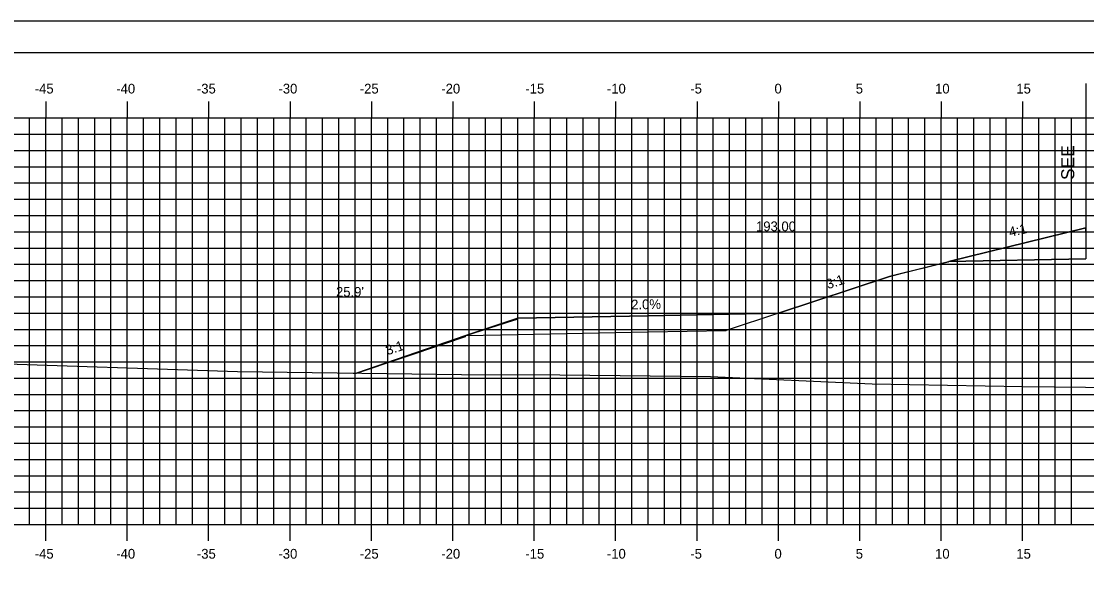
# Model space of a CAD drawing. Extents: x 1723764 to 1723936, y 458501 to 458611.
# Drawn here: x 1723801 to 1723866.5, y 458577.5 to 458611.2 of the extents above; entities that cross this region are included whole.
import ezdxf

# ---------------------------------------------------------------- set-up
doc = ezdxf.new("R2010")
doc.units = 0
for name, color, linetype in [('ANNOTATION', 7, 'Continuous'), ('BORDER', 7, 'Continuous'), ('D_Roadway_Centerline', 7, 'Continuous'), ('D_Roadway_Centerline_Text', 7, 'Continuous'), ('D_Roadway_Drive_Gravel', 7, 'Continuous'), ('D_Roadway_Edge_Shoulder', 7, 'Continuous'), ('D_Roadway_SlopeLines', 7, 'Continuous'), ('D_Roadway_SubGrade', 7, 'Continuous'), ('D_Text_Standard', 7, 'Continuous'), ('H_V ANNOTATION', 7, 'Continuous'), ('MAJOR', 7, 'Continuous'), ('MINOR', 7, 'Continuous'), ('PLOT BOUNDARY', 7, 'Continuous'), ('S_Roadway_Centerline', 7, 'Continuous')]:
    doc.layers.add(name, color=color, linetype=linetype)

msp = doc.modelspace()

# ---------------------------------------------------------------- linework, layer by layer
msp.add_lwpolyline([(1723821.421, 458589.561), (1723821.421, 458589.561), (1723821.615, 458589.558), (1723827.107, 458591.403), (1723828.318, 458591.81), (1723828.351, 458591.871), (1723828.35, 458591.871), (1723831.296, 458592.815), (1723831.513, 458592.887), (1723831.542, 458592.934), (1723839.542, 458593.094), (1723847.542, 458593.254), (1723847.542, 458593.254), (1723847.542, 458593.254)])
at = {"layer": 'BORDER'}
msp.add_lwpolyline([(1723772.542, 458504.254), (1723932.542, 458504.254), (1723932.542, 458609.254), (1723772.542, 458609.254)], close=True, dxfattribs=at)
at = {"layer": 'D_Roadway_Centerline'}
msp.add_lwpolyline([(1723847.542, 458593.254), (1723854.363, 458595.513), (1723855.146, 458595.707), (1723857.368, 458596.259), (1723857.45, 458596.279), (1723857.892, 458596.389), (1723857.983, 458596.412), (1723858.017, 458596.42), (1723862.494, 458597.531), (1723866.419, 458598.505)], dxfattribs=at)
at = {"layer": 'D_Roadway_Drive_Gravel'}
msp.add_lwpolyline([(1723847.542, 458593.254), (1723839.542, 458593.094), (1723831.542, 458592.934), (1723828.35, 458591.871), (1723831.542, 458591.934), (1723839.542, 458592.094), (1723844.328, 458592.19)], dxfattribs=at)
at = {"layer": 'D_Roadway_Edge_Shoulder'}
msp.add_line((1723866.419, 458598.505), (1723866.419, 458598.255), dxfattribs=at)
msp.add_line((1723866.419, 458598.505), (1723866.419, 458598.255), dxfattribs=at)
at = {"layer": 'D_Roadway_SlopeLines'}
msp.add_line((1723847.542, 458593.254), (1723844.328, 458592.19), dxfattribs=at)
for points in [[(1723866.419, 458598.505), (1723854.363, 458595.513), (1723847.542, 458593.254)], [(1723866.419, 458598.505), (1723854.363, 458595.513), (1723847.542, 458593.254)], [(1723866.419, 458598.505), (1723854.363, 458595.513), (1723847.542, 458593.254)], [(1723866.419, 458598.505), (1723854.363, 458595.513), (1723847.542, 458593.254)], [(1723866.419, 458598.505), (1723854.363, 458595.513), (1723847.542, 458593.254)], [(1723866.419, 458598.505), (1723854.363, 458595.513), (1723847.542, 458593.254)], [(1723866.419, 458598.505), (1723854.363, 458595.513)], [(1723866.419, 458598.505), (1723854.363, 458595.513)], [(1723866.419, 458598.505), (1723858.017, 458596.42)], [(1723847.542, 458593.254), (1723847.542, 458593.254)], [(1723831.542, 458592.934), (1723828.35, 458591.871), (1723821.615, 458589.558)]]:
    msp.add_lwpolyline(points, dxfattribs=at)
at = {"layer": 'D_Roadway_SubGrade'}
msp.add_line((1723866.419, 458607.364), (1723866.419, 458596.582), dxfattribs=at)
for points in [[(1723866.419, 458596.582), (1723858.017, 458596.42), (1723866.419, 458598.505), (1723866.419, 458598.255)], [(1723866.419, 458598.255), (1723866.419, 458598.505), (1723858.017, 458596.42), (1723866.419, 458596.582)], [(1723866.419, 458596.582), (1723858.017, 458596.42), (1723866.419, 458598.505), (1723866.419, 458598.255)], [(1723866.419, 458596.582), (1723858.017, 458596.42), (1723866.419, 458598.505), (1723866.419, 458598.255)]]:
    msp.add_lwpolyline(points, dxfattribs=at)
at = {"layer": 'MAJOR'}
for p, q in [((1723802.542, 458606.256), (1723802.542, 458605.254)), ((1723807.542, 458606.256), (1723807.542, 458605.254)), ((1723812.542, 458606.256), (1723812.542, 458605.254)), ((1723817.542, 458606.256), (1723817.542, 458605.254)), ((1723822.542, 458606.256), (1723822.542, 458605.254)), ((1723827.542, 458606.256), (1723827.542, 458605.254)), ((1723832.542, 458606.256), (1723832.542, 458605.254)), ((1723837.542, 458606.256), (1723837.542, 458605.254)), ((1723842.542, 458606.256), (1723842.542, 458605.254)), ((1723847.542, 458606.256), (1723847.542, 458605.254)), ((1723852.542, 458606.256), (1723852.542, 458605.254)), ((1723857.542, 458606.256), (1723857.542, 458605.254)), ((1723862.542, 458606.256), (1723862.542, 458605.254)), ((1723777.542, 458605.254), (1723917.542, 458605.254)), ((1723777.542, 458605.254), (1723917.542, 458605.254)), ((1723802.542, 458580.254), (1723802.542, 458605.254)), ((1723807.542, 458580.254), (1723807.542, 458605.254)), ((1723812.542, 458580.254), (1723812.542, 458605.254)), ((1723817.542, 458580.254), (1723817.542, 458605.254)), ((1723822.542, 458580.254), (1723822.542, 458605.254)), ((1723827.542, 458580.254), (1723827.542, 458605.254)), ((1723832.542, 458580.254), (1723832.542, 458605.254)), ((1723837.542, 458580.254), (1723837.542, 458605.254)), ((1723842.542, 458580.254), (1723842.542, 458605.254)), ((1723847.542, 458580.254), (1723847.542, 458605.254)), ((1723852.542, 458580.254), (1723852.542, 458605.254)), ((1723857.542, 458580.254), (1723857.542, 458605.254)), ((1723862.542, 458580.254), (1723862.542, 458605.254)), ((1723777.542, 458600.254), (1723917.542, 458600.254)), ((1723777.542, 458595.254), (1723917.542, 458595.254)), ((1723777.542, 458590.254), (1723917.542, 458590.254)), ((1723777.542, 458585.254), (1723917.542, 458585.254)), ((1723777.542, 458580.254), (1723917.542, 458580.254)), ((1723777.542, 458580.254), (1723917.542, 458580.254)), ((1723802.542, 458579.252), (1723802.542, 458580.254)), ((1723807.542, 458579.252), (1723807.542, 458580.254)), ((1723812.542, 458579.252), (1723812.542, 458580.254)), ((1723817.542, 458579.252), (1723817.542, 458580.254)), ((1723822.542, 458579.252), (1723822.542, 458580.254)), ((1723827.542, 458579.252), (1723827.542, 458580.254)), ((1723832.542, 458579.252), (1723832.542, 458580.254)), ((1723837.542, 458579.252), (1723837.542, 458580.254)), ((1723842.542, 458579.252), (1723842.542, 458580.254)), ((1723847.542, 458579.252), (1723847.542, 458580.254)), ((1723852.542, 458579.252), (1723852.542, 458580.254)), ((1723857.542, 458579.252), (1723857.542, 458580.254)), ((1723862.542, 458579.252), (1723862.542, 458580.254))]:
    msp.add_line(p, q, dxfattribs=at)
at = {"layer": 'MINOR'}
for p, q in [((1723801.542, 458580.254), (1723801.542, 458605.254)), ((1723803.542, 458580.254), (1723803.542, 458605.254)), ((1723804.542, 458580.254), (1723804.542, 458605.254)), ((1723805.542, 458580.254), (1723805.542, 458605.254)), ((1723806.542, 458580.254), (1723806.542, 458605.254)), ((1723808.542, 458580.254), (1723808.542, 458605.254)), ((1723809.542, 458580.254), (1723809.542, 458605.254)), ((1723810.542, 458580.254), (1723810.542, 458605.254)), ((1723811.542, 458580.254), (1723811.542, 458605.254)), ((1723813.542, 458580.254), (1723813.542, 458605.254)), ((1723814.542, 458580.254), (1723814.542, 458605.254)), ((1723815.542, 458580.254), (1723815.542, 458605.254)), ((1723816.542, 458580.254), (1723816.542, 458605.254)), ((1723818.542, 458580.254), (1723818.542, 458605.254)), ((1723819.542, 458580.254), (1723819.542, 458605.254)), ((1723820.542, 458580.254), (1723820.542, 458605.254)), ((1723821.542, 458580.254), (1723821.542, 458605.254)), ((1723823.542, 458580.254), (1723823.542, 458605.254)), ((1723824.542, 458580.254), (1723824.542, 458605.254)), ((1723825.542, 458580.254), (1723825.542, 458605.254)), ((1723826.542, 458580.254), (1723826.542, 458605.254)), ((1723828.542, 458580.254), (1723828.542, 458605.254)), ((1723829.542, 458580.254), (1723829.542, 458605.254)), ((1723830.542, 458580.254), (1723830.542, 458605.254)), ((1723831.542, 458580.254), (1723831.542, 458605.254)), ((1723833.542, 458580.254), (1723833.542, 458605.254)), ((1723834.542, 458580.254), (1723834.542, 458605.254)), ((1723835.542, 458580.254), (1723835.542, 458605.254)), ((1723836.542, 458580.254), (1723836.542, 458605.254)), ((1723838.542, 458580.254), (1723838.542, 458605.254)), ((1723839.542, 458580.254), (1723839.542, 458605.254)), ((1723840.542, 458580.254), (1723840.542, 458605.254)), ((1723841.542, 458580.254), (1723841.542, 458605.254)), ((1723843.542, 458580.254), (1723843.542, 458605.254)), ((1723844.542, 458580.254), (1723844.542, 458605.254)), ((1723845.542, 458580.254), (1723845.542, 458605.254)), ((1723846.542, 458580.254), (1723846.542, 458605.254)), ((1723848.542, 458580.254), (1723848.542, 458605.254)), ((1723849.542, 458580.254), (1723849.542, 458605.254)), ((1723850.542, 458580.254), (1723850.542, 458605.254)), ((1723851.542, 458580.254), (1723851.542, 458605.254)), ((1723853.542, 458580.254), (1723853.542, 458605.254)), ((1723854.542, 458580.254), (1723854.542, 458605.254)), ((1723855.542, 458580.254), (1723855.542, 458605.254)), ((1723856.542, 458580.254), (1723856.542, 458605.254)), ((1723858.542, 458580.254), (1723858.542, 458605.254)), ((1723859.542, 458580.254), (1723859.542, 458605.254)), ((1723860.542, 458580.254), (1723860.542, 458605.254)), ((1723861.542, 458580.254), (1723861.542, 458605.254)), ((1723863.542, 458580.254), (1723863.542, 458605.254)), ((1723864.542, 458580.254), (1723864.542, 458605.254)), ((1723865.542, 458580.254), (1723865.542, 458605.254)), ((1723777.542, 458604.254), (1723917.542, 458604.254)), ((1723777.542, 458603.254), (1723917.542, 458603.254)), ((1723777.542, 458602.254), (1723917.542, 458602.254)), ((1723777.542, 458601.254), (1723917.542, 458601.254)), ((1723777.542, 458599.254), (1723917.542, 458599.254)), ((1723777.542, 458598.254), (1723917.542, 458598.254)), ((1723777.542, 458597.254), (1723917.542, 458597.254)), ((1723777.542, 458596.254), (1723917.542, 458596.254)), ((1723777.542, 458594.254), (1723917.542, 458594.254)), ((1723777.542, 458593.254), (1723917.542, 458593.254)), ((1723777.542, 458592.254), (1723917.542, 458592.254)), ((1723777.542, 458591.254), (1723917.542, 458591.254)), ((1723777.542, 458589.254), (1723917.542, 458589.254)), ((1723777.542, 458588.254), (1723917.542, 458588.254)), ((1723777.542, 458587.254), (1723917.542, 458587.254)), ((1723777.542, 458586.254), (1723917.542, 458586.254)), ((1723777.542, 458584.254), (1723917.542, 458584.254)), ((1723777.542, 458583.254), (1723917.542, 458583.254)), ((1723777.542, 458582.254), (1723917.542, 458582.254)), ((1723777.542, 458581.254), (1723917.542, 458581.254))]:
    msp.add_line(p, q, dxfattribs=at)
at = {"layer": 'PLOT BOUNDARY'}
msp.add_lwpolyline([(1723764.449, 458501.195), (1723934.449, 458501.195), (1723934.449, 458611.195), (1723764.449, 458611.195)], close=True, dxfattribs=at)
at = {"layer": 'S_Roadway_Centerline'}
msp.add_lwpolyline([(1723777.542, 458590.535), (1723782.572, 458590.478), (1723794.565, 458590.362), (1723795.815, 458590.342), (1723798.304, 458590.194), (1723814.321, 458589.653), (1723828.082, 458589.474), (1723834.118, 458589.453), (1723843.37, 458589.361), (1723853.307, 458588.898), (1723862.561, 458588.74), (1723874.103, 458588.626), (1723880.292, 458588.403), (1723889.466, 458587.592), (1723891.167, 458587.447), (1723892.536, 458587.426), (1723903.57, 458587.401), (1723913.068, 458587.172), (1723915.267, 458587.202), (1723917.542, 458586.995)], dxfattribs=at)

# ---------------------------------------------------------------- texts
at = {"layer": 'ANNOTATION'}
for s, height, rotation, p in [('SEE', 0.8, 90, (1723865.716, 458601.438)), ('4:1', 0.6, 13.61624, (1723861.775, 458597.925)), ('3:1', 0.6, 18.43495, (1723850.589, 458594.719)), ('2.0%', 0.6, 1.14576, (1723838.505, 458593.474)), ('3:1', 0.6, 18.56865, (1723823.529, 458590.656))]:
    msp.add_text(s, height=height, rotation=rotation, dxfattribs=at).set_placement(p)
at = {"layer": 'D_Roadway_Centerline_Text'}
msp.add_text('193.00', height=0.6, dxfattribs=at).set_placement((1723846.167, 458598.286))
at = {"layer": 'D_Text_Standard'}
msp.add_text("25.9'", height=0.6, dxfattribs=at).set_placement((1723820.366, 458594.258))
at = {"layer": 'H_V ANNOTATION'}
for s, p in [('-45', (1723801.86, 458606.754)), ('-40', (1723806.868, 458606.754)), ('-35', (1723811.822, 458606.754)), ('-30', (1723816.83, 458606.754)), ('-25', (1723821.827, 458606.754)), ('-20', (1723826.835, 458606.754)), ('-15', (1723831.999, 458606.754)), ('-10', (1723837.007, 458606.754)), ('-5', (1723842.132, 458606.754)), ('0', (1723847.301, 458606.754)), ('5', (1723852.293, 458606.754)), ('10', (1723857.167, 458606.754)), ('15', (1723862.159, 458606.754)), ('-45', (1723801.86, 458578.154)), ('-40', (1723806.868, 458578.154)), ('-35', (1723811.822, 458578.154)), ('-30', (1723816.83, 458578.154)), ('-25', (1723821.827, 458578.154)), ('-20', (1723826.835, 458578.154)), ('-15', (1723831.999, 458578.154)), ('-10', (1723837.007, 458578.154)), ('-5', (1723842.132, 458578.154)), ('0', (1723847.301, 458578.154)), ('5', (1723852.293, 458578.154)), ('10', (1723857.167, 458578.154)), ('15', (1723862.159, 458578.154))]:
    msp.add_text(s, height=0.6, dxfattribs=at).set_placement(p)

doc.saveas('drawing.dxf')
